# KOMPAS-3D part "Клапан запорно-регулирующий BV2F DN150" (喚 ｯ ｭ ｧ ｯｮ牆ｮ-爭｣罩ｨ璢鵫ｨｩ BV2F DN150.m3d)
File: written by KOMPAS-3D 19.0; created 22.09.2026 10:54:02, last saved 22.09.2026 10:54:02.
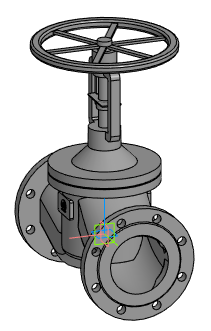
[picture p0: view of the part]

Document properties: Автор: Энергия; Полное имя файла: Z:\3.Личные\sachek\Dendor\_3D для проектировщиков\5.7 Клапан запорно-регулирующий BV2F\BV2F_STP\Клапан запорно-регулирующий BV2F DN150.m3d

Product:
- Part/product: Клапан запорно-регулирующий BV2F DN150

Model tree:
1. Операция без истории:1  (labels: Клапан запорно-регулирующий BV2F DN150)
